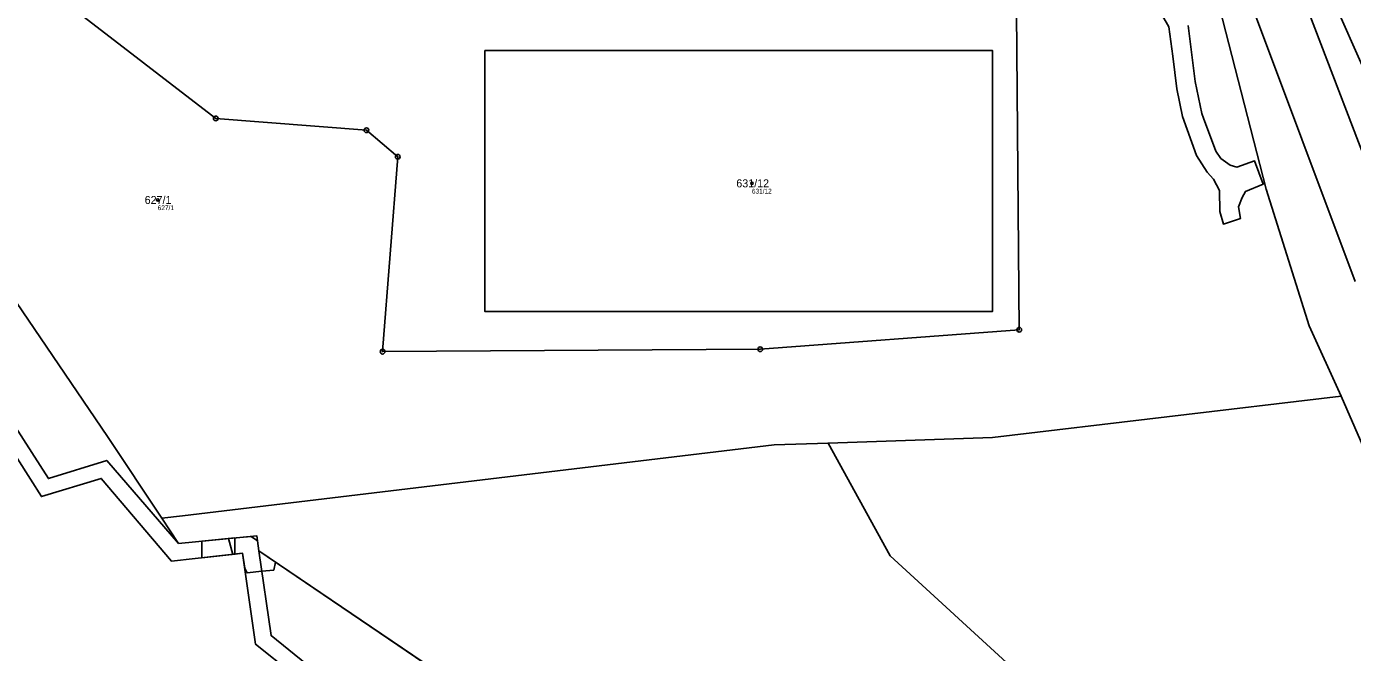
# Model space of a CAD drawing. Extents: x -653098 to -649479, y -997642 to -992666.
# Drawn here: x -652431.3 to -652149.5, y -995348.3 to -995215.3 of the extents above; entities that cross this region are included whole.
import ezdxf

# ---------------------------------------------------------------- set-up
doc = ezdxf.new("R2010")
doc.units = 0
for name, color, linetype in [('Definiční body', 7, 'Continuous'), ('Hranice parcel', 7, 'Continuous'), ('Parcelní čísla', 7, 'Continuous'), ('Polygon ku', 7, 'Continuous'), ('Polygon parcely', 7, 'Continuous'), ('Vnitřní kresba', 7, 'Continuous'), ('Věcná břemena k části', 7, 'Continuous'), ('Značky bodu BP', 7, 'Continuous')]:
    doc.layers.add(name, color=color, linetype=linetype)

msp = doc.modelspace()

# ---------------------------------------------------------------- linework, layer by layer
at = {"layer": 'Definiční body'}
for centre in [(-652277.14, -995248.64), (-652403.38, -995252.17)]:
    msp.add_circle(centre, 0.25, dxfattribs=at)
at = {"layer": 'Hranice parcel'}
for p, q in [((-652260.94, -995303.82), (-652272.44, -995304.18)), ((-652402.51, -995319.79), (-652398.95, -995325.15)), ((-652294.5, -995385.96), (-652381.86, -995326.75))]:
    msp.add_line(p, q, dxfattribs=at)
for points in [[(-652220.95, -995212.17), (-652220.34, -995279.76), (-652275.38, -995283.89), (-652355.61, -995284.4), (-652352.37, -995242.99), (-652359.03, -995237.34), (-652391.05, -995234.85), (-652421.78, -995211.17), (-652435.22, -995187.46), (-652437.9, -995168.78), (-652435.61, -995162.27), (-652444.63, -995081.54), (-652439.29, -995061.56), (-652428.01, -995044.33), (-652420.16, -995037.52), (-652410.96, -995032.19), (-652393.56, -995027.18), (-652345.14, -995026.66)], [(-652151.93, -995293.89), (-652158.75, -995278.94), (-652167.9, -995249.85), (-652177.81, -995211.25), (-652182.75, -995195.81), (-652183.99, -995192.16)], [(-652158.1, -995199.61), (-652142.43, -995234.93), (-652130.27, -995262.01), (-652110.1, -995319.26)], [(-652484.64, -995199.93), (-652457, -995231.85), (-652451.58, -995247.22), (-652414.06, -995302.42), (-652402.51, -995319.79)], [(-652184.47, -995215.12), (-652182.96, -995227), (-652181.54, -995233.81), (-652181.23, -995234.78), (-652178.61, -995241.78), (-652177.5, -995243.38), (-652175.54, -995244.78), (-652174.12, -995245.21), (-652170.33, -995243.86), (-652168.51, -995248.79), (-652172.26, -995250.34), (-652172.99, -995251.63), (-652173.73, -995253.65), (-652173.33, -995256.08), (-652176.96, -995257.28), (-652177.72, -995254.64), (-652177.79, -995250.13), (-652179.1, -995247.73), (-652180.39, -995246.25), (-652182.65, -995242.69), (-652185.66, -995234.45), (-652186.86, -995228.53), (-652187.71, -995221.62), (-652188.59, -995215.36), (-652189.91, -995213.03)], [(-652398.95, -995325.15), (-652414.21, -995307.49), (-652426.61, -995311.38), (-652438.39, -995293.04), (-652457.3, -995298.47), (-652466.98, -995285.01), (-652468.41, -995276.05), (-652466.69, -995266.24), (-652465.98, -995262.41), (-652473.44, -995261.89), (-652477.98, -995244.34), (-652496.99, -995222.77), (-652502.08, -995217.71), (-652512.35, -995224.1), (-652519.27, -995220.98)], [(-652333.91, -995220.39), (-652226.04, -995220.38), (-652226.01, -995275.84), (-652333.88, -995275.9), (-652333.91, -995220.39)], [(-652151.93, -995293.89), (-652226.03, -995302.63), (-652260.94, -995303.82)], [(-652151.93, -995293.89), (-652133.09, -995337.03), (-652115.66, -995375.94), (-652106.25, -995403.56)], [(-652456.83, -995301.64), (-652439.8, -995296.77), (-652428.08, -995315.2), (-652415.39, -995311.32), (-652400.46, -995328.91), (-652385.33, -995327.24), (-652382.58, -995346.57)], [(-652106.25, -995403.56), (-652138.79, -995409.66), (-652177.57, -995394.65), (-652218.02, -995370.04), (-652220.52, -995352.81), (-652247.76, -995327.79), (-652260.94, -995303.82)], [(-652272.44, -995304.18), (-652398.1, -995319.26), (-652402.51, -995319.79)], [(-652381.86, -995326.75), (-652382.32, -995323.53), (-652398.95, -995325.15)], [(-652381.86, -995326.75), (-652379.31, -995344.72), (-652350.74, -995367.86), (-652346.96, -995377.17), (-652328.89, -995375.95), (-652332.77, -995388.15), (-652308.65, -995396.42), (-652294.5, -995385.96)], [(-652382.58, -995346.57), (-652374.62, -995352.95), (-652353.48, -995369.89)]]:
    msp.add_lwpolyline(points, dxfattribs=at)
at = {"layer": 'Polygon ku'}
msp.add_lwpolyline([(-652439.8, -995296.77), (-652428.08, -995315.2), (-652415.39, -995311.32), (-652400.46, -995328.91), (-652385.33, -995327.24), (-652382.58, -995346.57), (-652374.62, -995352.95)], dxfattribs=at)
at = {"layer": 'Polygon parcely'}
for points in [[(-652451.58, -995247.22), (-652414.06, -995302.42), (-652402.51, -995319.79), (-652398.1, -995319.26), (-652272.44, -995304.18), (-652260.94, -995303.82), (-652226.03, -995302.63), (-652151.93, -995293.89), (-652158.75, -995278.94), (-652167.9, -995249.85), (-652177.81, -995211.25), (-652182.75, -995195.81), (-652183.99, -995192.16), (-652188.33, -995179.46), (-652201.45, -995145.65), (-652203.6, -995140.1)], [(-652094.76, -995364.87), (-652109.11, -995322.54), (-652110.1, -995319.26), (-652130.27, -995262.01), (-652142.43, -995234.93), (-652158.1, -995199.61), (-652160.09, -995195.35), (-652165.58, -995194.55), (-652170.15, -995193.88), (-652177.64, -995192.95), (-652183.99, -995192.16), (-652182.75, -995195.81), (-652177.81, -995211.25), (-652167.9, -995249.85), (-652158.75, -995278.94), (-652151.93, -995293.89), (-652133.09, -995337.03), (-652115.66, -995375.94)], [(-652421.78, -995211.17), (-652391.05, -995234.85), (-652359.03, -995237.34), (-652352.37, -995242.99), (-652355.61, -995284.4), (-652275.38, -995283.89), (-652220.34, -995279.76), (-652220.95, -995212.17)], [(-652220.95, -995212.17), (-652220.34, -995279.76), (-652275.38, -995283.89), (-652355.61, -995284.4), (-652352.37, -995242.99), (-652359.03, -995237.34), (-652391.05, -995234.85), (-652421.78, -995211.17)], [(-652189.91, -995213.03), (-652188.59, -995215.36), (-652187.71, -995221.62), (-652186.86, -995228.53), (-652185.66, -995234.45), (-652182.65, -995242.69), (-652180.39, -995246.25), (-652179.1, -995247.73), (-652177.79, -995250.13), (-652177.72, -995254.64), (-652176.96, -995257.28), (-652173.33, -995256.08), (-652173.73, -995253.65), (-652172.99, -995251.63), (-652172.26, -995250.34), (-652168.51, -995248.79), (-652170.33, -995243.86), (-652174.12, -995245.21), (-652175.54, -995244.78), (-652177.5, -995243.38), (-652178.61, -995241.78), (-652181.23, -995234.78), (-652181.54, -995233.81), (-652182.96, -995227), (-652184.47, -995215.12)], [(-652184.47, -995215.12), (-652182.96, -995227), (-652181.54, -995233.81), (-652181.23, -995234.78), (-652178.61, -995241.78), (-652177.5, -995243.38), (-652175.54, -995244.78), (-652174.12, -995245.21), (-652170.33, -995243.86), (-652168.51, -995248.79), (-652172.26, -995250.34), (-652172.99, -995251.63), (-652173.73, -995253.65), (-652173.33, -995256.08), (-652176.96, -995257.28), (-652177.72, -995254.64), (-652177.79, -995250.13), (-652179.1, -995247.73), (-652180.39, -995246.25), (-652182.65, -995242.69), (-652185.66, -995234.45), (-652186.86, -995228.53), (-652187.71, -995221.62), (-652188.59, -995215.36), (-652189.91, -995213.03)], [(-652350.74, -995367.86), (-652379.31, -995344.72), (-652381.86, -995326.75), (-652382.32, -995323.53), (-652398.95, -995325.15), (-652414.21, -995307.49), (-652426.61, -995311.38), (-652438.39, -995293.04)], [(-652439.8, -995296.77), (-652428.08, -995315.2), (-652415.39, -995311.32), (-652400.46, -995328.91), (-652385.33, -995327.24), (-652382.58, -995346.57), (-652374.62, -995352.95)]]:
    msp.add_lwpolyline(points, dxfattribs=at)
for points in [[(-652087.66, -995328.29), (-652094.36, -995317.97), (-652094.85, -995227.21), (-652110.65, -995234.12), (-652135.34, -995243.43), (-652142.17, -995225.55), (-652097.93, -995208.09), (-652075.25, -995202.59), (-652071.16, -995199.48), (-652110.68, -995203.8), (-652117.97, -995203.4), (-652150.58, -995200.78), (-652158.1, -995199.61), (-652142.43, -995234.93), (-652130.27, -995262.01), (-652110.1, -995319.26), (-652087.84, -995336.87), (-652078.7, -995341.49), (-652068.09, -995346.35)], [(-652484.64, -995199.93), (-652513.48, -995217.46), (-652519.27, -995220.98), (-652512.35, -995224.1), (-652502.08, -995217.71), (-652496.99, -995222.77), (-652477.98, -995244.34), (-652473.44, -995261.89), (-652465.98, -995262.41), (-652466.69, -995266.24), (-652468.41, -995276.05), (-652466.98, -995285.01), (-652457.3, -995298.47), (-652438.39, -995293.04), (-652426.61, -995311.38), (-652414.21, -995307.49), (-652398.95, -995325.15), (-652402.51, -995319.79), (-652414.06, -995302.42), (-652451.58, -995247.22), (-652457, -995231.85)], [(-652333.91, -995220.39), (-652226.04, -995220.38), (-652226.01, -995275.84), (-652333.88, -995275.9)], [(-652333.91, -995220.39), (-652333.88, -995275.9), (-652226.01, -995275.84), (-652226.04, -995220.38)], [(-652151.93, -995293.89), (-652226.03, -995302.63), (-652260.94, -995303.82), (-652247.76, -995327.79), (-652220.52, -995352.81), (-652218.02, -995370.04), (-652177.57, -995394.65), (-652138.79, -995409.66), (-652106.25, -995403.56), (-652115.66, -995375.94), (-652133.09, -995337.03)], [(-652398.1, -995319.26), (-652402.51, -995319.79), (-652398.95, -995325.15), (-652382.32, -995323.53), (-652381.86, -995326.75), (-652294.5, -995385.96), (-652278.63, -995397.72), (-652236.44, -995400.25), (-652221.03, -995417.86), (-652156.39, -995412.86), (-652122.99, -995412.67), (-652102.8, -995413.74), (-652103.27, -995412.32), (-652106.25, -995403.56), (-652138.79, -995409.66), (-652177.57, -995394.65), (-652218.02, -995370.04), (-652220.52, -995352.81), (-652247.76, -995327.79), (-652260.94, -995303.82), (-652272.44, -995304.18)], [(-652381.86, -995326.75), (-652379.31, -995344.72), (-652350.74, -995367.86), (-652346.96, -995377.17), (-652328.89, -995375.95), (-652332.77, -995388.15), (-652308.65, -995396.42), (-652294.5, -995385.96)]]:
    msp.add_lwpolyline(points, close=True, dxfattribs=at)
at = {"layer": 'Vnitřní kresba'}
for p, q in [((-652177.64, -995192.95), (-652148.98, -995269.47)), ((-652165.58, -995194.55), (-652138.45, -995265.66))]:
    msp.add_line(p, q, dxfattribs=at)
at = {"layer": 'Věcná břemena k části'}
for points in [[(-652393.98, -995324.67), (-652393.99, -995328.2), (-652386.99, -995327.42), (-652386.98, -995323.98)], [(-652388.36, -995324.12), (-652387.44, -995327.47), (-652385.33, -995327.24), (-652384.88, -995330.4), (-652384.38, -995331.37), (-652381.25, -995331.05), (-652378.72, -995330.8), (-652378.35, -995329.13), (-652381.86, -995326.75), (-652382.17, -995324.59), (-652383.49, -995323.64)]]:
    msp.add_lwpolyline(points, close=True, dxfattribs=at)
at = {"layer": 'Značky bodu BP'}
for centre, radius in [((-652391.05, -995234.85), 0.5), ((-652391.05, -995234.85), 0.0303), ((-652359.03, -995237.34), 0.5), ((-652359.03, -995237.34), 0.0303), ((-652352.37, -995242.99), 0.5), ((-652352.37, -995242.99), 0.0303), ((-652220.34, -995279.76), 0.5), ((-652220.34, -995279.76), 0.0303), ((-652355.61, -995284.4), 0.5), ((-652275.38, -995283.89), 0.5), ((-652275.38, -995283.89), 0.0303), ((-652355.61, -995284.4), 0.0303)]:
    msp.add_circle(centre, radius, dxfattribs=at)

# ---------------------------------------------------------------- texts
at = {"layer": 'Definiční body'}
for s, p in [('631/12', (-652277.14, -995250.8)), ('627/1', (-652403.38, -995254.33))]:
    msp.add_text(s, height=1, dxfattribs=at).set_placement(p)
at = {"layer": 'Parcelní čísla'}
for s, p in [('631/12', (-652280.45, -995249.49)), ('627/1', (-652406.15, -995253.02))]:
    msp.add_text(s, height=1.7, dxfattribs=at).set_placement(p)

doc.saveas('drawing.dxf')
